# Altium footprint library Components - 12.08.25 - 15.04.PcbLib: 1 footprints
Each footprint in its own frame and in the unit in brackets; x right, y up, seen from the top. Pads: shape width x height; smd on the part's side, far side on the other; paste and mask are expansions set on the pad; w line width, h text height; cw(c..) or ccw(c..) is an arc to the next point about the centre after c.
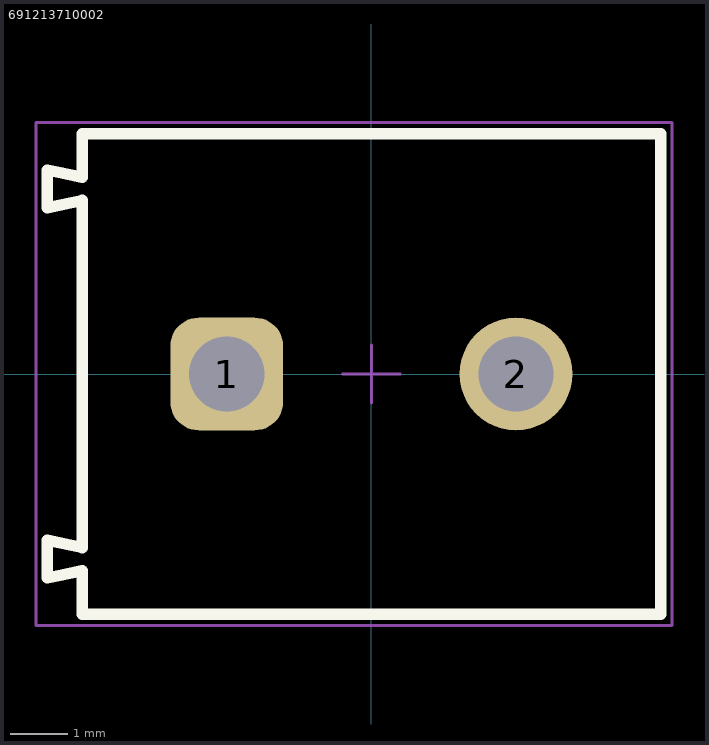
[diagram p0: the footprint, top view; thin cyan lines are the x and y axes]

## 691213710002 [mm] "5,00mm - modular - green - Horizontal entry with rising cage clamp -  10,0mm height - 02p"
height 10
pads (2):
  rrect50% 1.95x1.95 hole 1.3: 1(-2.5,0)
  round 1.95 hole 1.3: 2(2.5,0)
Top Overlay:
  lines w0.2: -5.6,-3.525 -5,-3.4 -5,-4.15 5,-4.15 5,4.15 -5,4.15 -5,3.4 -5.6,3.525 -5.6,2.875 -5,3 -5,-3 -5.6,-2.875 -5.6,-3.525
Top Designator:
  text ".Designator" at -7.498,-0.5 h1.5
Top Component Outline:
  lines w0.1: -5.6,-3.525 -5.6,-2.875 -5,-3 -5,3 -5.6,2.875 -5.6,3.525 -5,3.4 -5,4.15 5,4.15 5,-4.15 -5,-4.15 -5,-3.4 -5.6,-3.525
Top 3D Body:
  lines w0.1: -5.6,-3.525 -5,-3.4 -5,-4.15 5,-4.15 5,4.15 -5,4.15 -5,3.4 -5.6,3.525 -5.6,2.875 -5,3 -5,-3 -5.6,-2.875 -5.6,-3.525
Top Courtyard:
  lines w0.05: -5.8,-4.35 -5.8,4.35 5.2,4.35 5.2,-4.35 -5.8,-4.35
Top Component Center:
  lines w0.05: -0.5,0 0.5,0 ; 0,-0.5 0,0.5
3D body "691213710002.stp": height 10.05, standoff -3.75, extent -5.6,-4.15 5,4.15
